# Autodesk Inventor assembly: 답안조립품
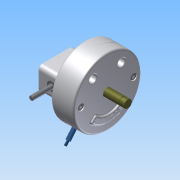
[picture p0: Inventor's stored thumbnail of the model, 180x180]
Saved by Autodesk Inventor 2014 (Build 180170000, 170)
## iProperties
Created: 2015-04
Part Number: 답안조립품
Document SubType Name: Assembly
Designer: Administrator
Mass: 1552.6 g
Surface Area: 3333.71 cm^2
Volume: 1140.85 cm^3
Density: 1.36092 g/cm^3
Author: Administrator
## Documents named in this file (15)
- C:\Documents and Settings\Administrator\바탕 화면\350406V1042\답안조립품.iam
- C:\Documents and Settings\Administrator\바탕 화면\350406V1042\본체.ipt
- C:\Documents and Settings\Administrator\바탕 화면\350406V1042\커버.ipt
- C:\Documents and Settings\Administrator\바탕 화면\350406V1042\베어링62_22.ipt
- C:\Documents and Settings\Administrator\바탕 화면\350406V1042\축.ipt
- C:\Documents and Settings\Administrator\바탕 화면\350406V1042\멈춤링.ipt
- C:\Documents and Settings\Administrator\바탕 화면\350406V1042\슬라이더2.ipt
- C:\Documents and Settings\Administrator\바탕 화면\350406V1042\슬라이더.ipt
- C:\Documents and Settings\Administrator\바탕 화면\350406V1042\평행핀.ipt
- C:\Documents and Settings\Administrator\바탕 화면\350406V1042\부시.ipt
- C:\Documents and Settings\Administrator\바탕 화면\350406V1042\슬라이더3.ipt
- C:\Documents and Settings\Administrator\바탕 화면\350406V1042\스프링-[가변].ipt
- C:\Documents and Settings\Administrator\바탕 화면\350406V1042\커버2.ipt
- C:\Documents and Settings\Administrator\바탕 화면\350406V1042\M 10 x 35.ipt
- C:\Documents and Settings\Administrator\바탕 화면\350406V1042\M 5 x 12.ipt
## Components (5 placed, 3 different names)
1. KS B 1320 B B 5 x  20:1
2. M 10 x 35:1
3. M 10 x 35:2
4. M 5 x 12:1
5. M 5 x 12:2
